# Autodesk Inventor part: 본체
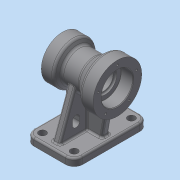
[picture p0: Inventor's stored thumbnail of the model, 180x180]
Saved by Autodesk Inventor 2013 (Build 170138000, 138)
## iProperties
Created: 2015-08
Part Number: 본체
Material: 일반
Document SubType Name: Modeling
Designer: Administrator
Density: 1 g/cm^3
Author: Administrator
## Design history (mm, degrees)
sketch "스케치1"
  geometry: L1 (0, 0)-(90, 0); L2 (0, 0)-(0, 35); L3 (0, 35)-(20, 35); L4 (20, 35)-(25.196, 26); L5 (25.196, 26)-(53.315, 26); L6 (53.315, 26)-(70, 40); L7 (70, 40)-(90, 40); L8 (90, 40)-(90, 0)
  constraints: 16 end point, 3 parallel, 2 perpendicular, 1 horizontal
  dimensions: "d0" = 90 distance of L1.start L1.end; "d1" = 70 diameter of L3 L1; "d2" = 20 distance of L2.end L3.end; "d3" = 60 deg angle of L5 L4; "d4" = 20 distance of L6.end L7.end; "d5" = 80 diameter of L7 L1; "d6" = 40 deg angle of L5 L6; "d7" = 52 diameter of L5 L1
revolve "회전1" sketch "스케치1" stored, may be unused: angle "d8" = 90 deg
sketch "스케치2"
  geometry: L1 (-61, -78)-(61, -78); L2 (61, -78)-(61, -90); L3 (61, -90)-(-61, -90); L4 (-61, -90)-(-61, -78); 2 further points
  constraints: 8 end point, 2 parallel, 1 horizontal, 1 midpoint, 1 perpendicular, 1 vertical alignment
  dimensions: "d9" = 90 distance from line of L3 point (0, 0); "d10" = 12 distance of L3.end L1.start; "d11" = 122 distance of L2.end L3.end
extrude "돌출1" join sketch "스케치2" distance "d12" = 80; taper "d13" = 0 deg
node "작업 평면1"
sketch "스케치3"
  geometry: L1 (-6, 0)-(6, 0); L2 (6, 0)-(6, -78); L3 (6, -78)-(-6, -78); L4 (-6, -78)-(-6, 0); L5 (-61, -90)-(-61, -78) reference; L6 (-61, -78)-(61, -78) reference; L7 (61, -78)-(61, -90) reference; L8 (61, -90)-(-61, -90) reference; C1 r 26 at (0, 0) reference; 2 further points
  constraints: 8 end point, 2 coincident, 2 parallel, 1 collinear, 1 horizontal, 1 midpoint, 1 perpendicular
  dimensions: "d14" = 12 distance of L1.start L1.end
extrude "돌출2" join sketch "스케치3" distance "d16" = 30; taper "d18" = 0 deg; dims "d17" = 30, "d19" = 0
sketch "스케치4"
  geometry: L1 (0, 35)-(0, -35) reference; L2 (0, -35)-(-10, -35) reference; L3 (-10, -35)-(-10, -78) reference; L4 (-10, -78)-(0, -78) reference; L5 (0, -78)-(0, -90) reference; L6 (0, -90)-(-80, -90) reference; L7 (-80, -90)-(-80, -78) reference; L8 (-80, -78)-(-70, -78) reference; L9 (-70, -78)-(-70, -40) reference; L10 (-70, -40)-(-90, -40) reference; L11 (-90, -40)-(-90, 40) reference; L12 (-90, 40)-(-70, 40) reference; L13 (-70, 40)-(-53.315, 26) reference; L14 (-53.315, 26)-(-25.196, 26) reference; L15 (-25.196, 26)-(-20, 35) reference; L16 (-20, 35)-(0, 35) reference; L17 (-70, -78)-(-76.7, -40); 1 further point
  constraints: 2 end point, 1 point on line
  dimensions: "d20" = 80 deg angle of L17 L8
feature "리브1" sketch "스케치4" dims "d21" = 1, "d22" = 12, "d23" = 0, "d24" = 0, "d25" = 1, "d26" = 1
sketch "스케치5"
  geometry: L1 (0, -35)-(-10, -35) reference; L2 (-10, -35)-(-10, -78) reference; L3 (-10, -78)-(0, -78) reference; L4 (0, -78)-(0, -90) reference; L5 (0, -90)-(-80, -90) reference; L6 (-80, -90)-(-80, -78) reference; L7 (-80, -78)-(-70, -78) reference; L8 (-70, -78)-(-76.7, -40) reference; L9 (-76.7, -40)-(-90, -40) reference; L10 (-90, -40)-(-90, 40) reference; L11 (-90, 40)-(-70, 40) reference; L12 (-70, 40)-(-53.315, 26) reference; L13 (-53.315, 26)-(-25.196, 26) reference; L14 (-25.196, 26)-(-20, 35) reference; L15 (-20, 35)-(0, 35) reference; L16 (0, 35)-(0, -35) reference; 1 further point
  node "절단 모서리 투영3"
sketch "스케치6"
  geometry: L1 (6, -78)-(61, -78) reference; L2 (61, -78)-(61, -90) reference; L3 (61, -90)-(-61, -90) reference; L4 (-61, -90)-(-61, -78) reference; L5 (-61, -78)-(-6, -78) reference; L6 (-6, -78)-(-6, -25.298) reference; L7 (6, -25.298)-(6, -78) reference; L8 (-51, -78)-(-25.92, -9.094); A1 r 26 centre (0, 0) between (6, -25.298) and (-6, -25.298) reference; 1 further point
  constraints: 2 end point, 1 point on line
  dimensions: "d27" = 70 deg angle of L5 L8; "d28" = 10 distance from line of L8.start L4
feature "리브2" sketch "스케치6" dims "d29" = 1, "d30" = 12, "d31" = 0, "d32" = 0, "d33" = 1, "d34" = 1
fillet "모깎기1" dims "d35" = 14
hole "구멍1" diameter "d38" = 38; stored, may be unused: countersink angle "d42" = 90 deg, drill point angle "d44" = 0 deg; dims "d36" = 10, "d37" = 10, "d39" = 6, "d40" = 52, "d41" = 20, "d43" = 23
hole "구멍2" diameter "d47" = 32; stored, may be unused: countersink angle "d51" = 90 deg, drill point angle "d53" = 0 deg; dims "d45" = 10, "d46" = 10, "d48" = 6, "d49" = 40, "d50" = 17, "d52" = 23
sketch "스케치7"
  geometry: C1 r 20 at (0, 0) reference; 1 further point
  constraints: 1 horizontal alignment
  dimensions: "d54" = 27 distance of C1.centre point (27, 0)
hole "구멍3" sketch "스케치7" at (27, 0) diameter "d55" = 3.242; stored, may be unused: countersink angle "d59" = 90 deg, drill point angle "d61" = 118 deg; dims "d56" = 10, "d57" = 40, "d58" = 17, "d60" = 13
sketch "스케치8"
  geometry: C1 r 26 at (0, 0) reference; 1 further point
  constraints: 1 horizontal alignment
  dimensions: "d65" = 33 distance of C1.centre point (-33, 0)
hole "구멍4" sketch "스케치8" at (-33, 0) diameter "d66" = 3.242; stored, may be unused: countersink angle "d70" = 90 deg, drill point angle "d72" = 118 deg; dims "d67" = 10, "d68" = 40, "d69" = 17, "d71" = 13
fillet "모깎기2" dims "d76" = 5
fillet "모깎기3" dims "d77" = 3
chamfer "모따기1" distance "d78" = 1; stored, may be unused: second distance "d79" = 2, angle "d80" = 45 deg
fillet "모깎기4" dims "d81" = 0.3
sketch "스케치9"
  geometry: L1 (0, 45)-(0, 0) reference; L2 (-30, 12)-(-12, 12); L3 (-12, 12)-(-12, 24); L4 (-12, 24)-(-30, 24); L5 (-30, 24)-(-30, 12); L6 (-30, 18)-(-12, 18); L7 (-21, 12)-(-21, 24); A1 r 26 centre (-78, -6) between (-52.702, 0) and (-71.185, 19.091) reference
  constraints: 12 end point, 4 midpoint, 2 parallel, 1 horizontal, 1 perpendicular
  dimensions: "d82" = 12 distance of L4.end L2.start; "d84" = 18 distance of L2.start L2.end; "d85" = 24 vertical distance of A1.centre L6.end; "d86" = 21 distance between parallel lines of L1 L7
extrude "돌출3" cut sketch "스케치9" stored distance "d87" = 12; taper "d88" = 0 deg
fillet "모깎기5" dims "d89" = 6
sketch "스케치10"
  geometry: C1 r 6 at (14, 0); C2 r 6 at (14, 94); C3 r 6 at (66, 94); C4 r 6 at (66, 0); A1 r 14 centre (14, 94) between (14, 108) and (0, 94) reference; A2 r 14 centre (14, 0) between (0, 0) and (14, -14) reference; A3 r 14 centre (66, 0) between (66, -14) and (80, 0) reference; A4 r 14 centre (66, 94) between (80, 94) and (66, 108) reference; 1 further point
  constraints: 4 centre point, 4 coincident, 3 equal radius
  dimensions: "d90" = 12 diameter of C1
extrude "돌출4" cut sketch "스케치10" stored distance "d92" = 12; taper "d93" = 0 deg
fillet "모깎기6" dims "d94" = 3
fillet "모깎기7" dims "d95" = 3
sketch "스케치11"
  geometry: L1 (-10, -3)-(1, -3) reference; L2 (-3, 37.119)-(-3, 0) reference; 2 further points
  constraints: 1 other
  dimensions: "d96" = 24 distance from line of point (13, 21) L1; "d97" = 16 distance from line of point (13, 21) L2
feature "엠보싱1" sketch "스케치11" dims "d0" = 90, "d1" = 70, "d2" = 20, "d3" = 60 deg, "d4" = 20, "d5" = 80, "d6" = 40 deg, "d7" = 52, "d98" = 0.5, "d99" = 0
node "솔리드1"
mirror "대칭1"
pattern_circular "원형 패턴1" dims angle "d63" = 360 deg
pattern_circular "원형 패턴2" dims angle "d74" = 360 deg
mirror "대칭2"
node "절단 모서리 투영1"
node "절단 모서리 투영2"
node "절단 모서리 투영4"
